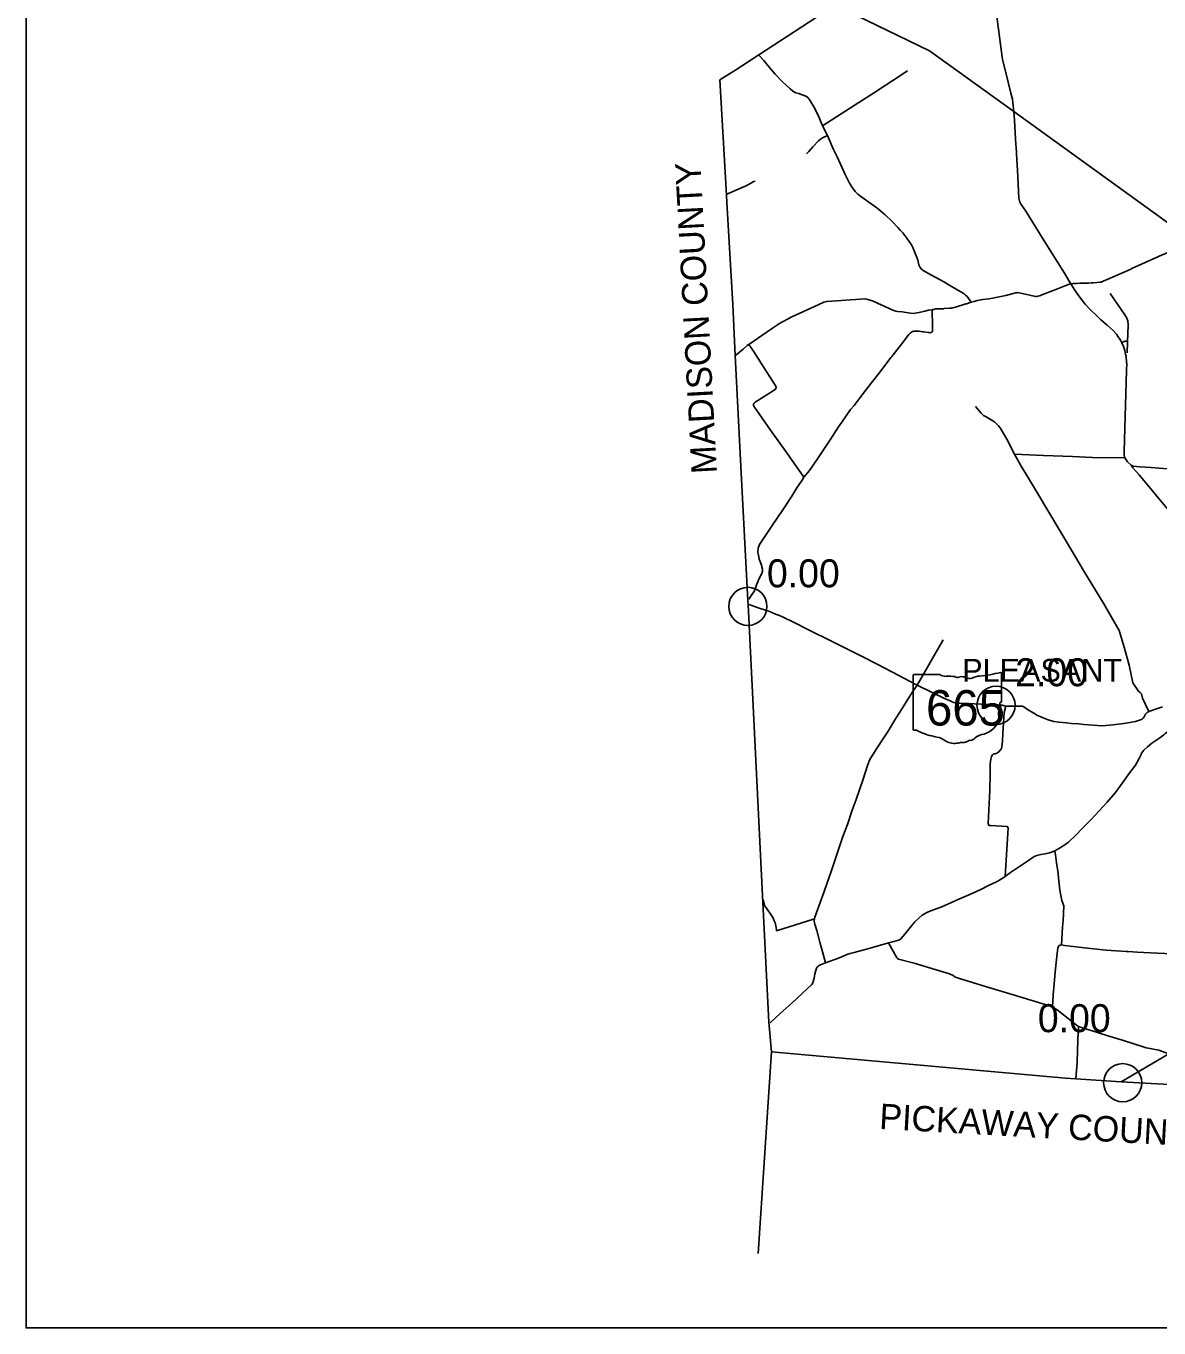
# Model space of a CAD drawing. Extents: x 1729596 to 1934326, y 644115 to 911751.
# Drawn here: x 1730291 to 1774831, y 650175 to 701344 of the extents above; entities that cross this region are included whole.
import ezdxf

# ---------------------------------------------------------------- set-up
doc = ezdxf.new("R2010")
doc.units = 0
for name, color, linetype in [('Default', 7, 'Continuous'), ('GM_X_Adjacent_County', 7, 'Continuous'), ('GM_X_Adjacent_County_Text', 7, 'Continuous'), ('GM_X_County', 7, 'Continuous'), ('GM_X_County_Road', 7, 'Continuous'), ('GM_X_Interstate_Route', 7, 'Continuous'), ('GM_X_State_Route', 7, 'Continuous'), ('GM_X_State_Shield', 7, 'Continuous'), ('GM_X_Township', 7, 'Continuous'), ('GM_X_Township_Road', 7, 'Continuous'), ('GM_X_Township_Text', 7, 'Continuous'), ('SC_Scratch1', 7, 'Continuous')]:
    doc.layers.add(name, color=color, linetype=linetype)

msp = doc.modelspace()

# ---------------------------------------------------------------- linework, layer by layer
at = {"layer": 'Default'}
for centre in [(1758669, 678534), (1758669, 678534), (1768427, 674646), (1773406, 659814), (1773406, 659814)]:
    msp.add_circle(centre, 750, dxfattribs=at)
at = {"layer": 'GM_X_Adjacent_County'}
msp.add_line((1759596, 661027), (1759070, 653104), dxfattribs=at)
at = {"layer": 'GM_X_County'}
msp.add_lwpolyline([(1779741, 659492), (1773339, 659850), (1771560, 659962), (1771157, 659994), (1759596, 661027), (1759497, 662188), (1759258, 666902), (1758681, 678614), (1758672, 678766), (1758400, 683790), (1758170, 688397), (1758072, 690399), (1757841, 694414), (1757825, 694698), (1757564, 699226), (1758151, 699596), (1759102, 700215), (1763614, 703154)], dxfattribs=at)
at = {"layer": 'GM_X_County_Road'}
for points in [[(1769211, 696603), (1769207, 696674), (1769146, 697650), (1769123, 697982), (1769092, 698322), (1769069, 698471), (1769011, 698712), (1768797, 699571), (1768694, 699972), (1768678, 700045), (1768665, 700116), (1768455, 701718), (1768288, 702977), (1767960, 705470), (1767928, 705663), (1767674, 707564), (1767277, 710453)], [(1759118, 700191), (1759294, 699984), (1759452, 699796), (1759742, 699454), (1760015, 699169), (1760338, 698875), (1760441, 698789), (1760561, 698723), (1760671, 698692), (1760765, 698659), (1760887, 698616), (1760969, 698580), (1761030, 698531), (1761109, 698430), (1761262, 698171), (1761420, 697873), (1761607, 697416), (1761797, 697046), (1762028, 696515), (1762193, 696174), (1762475, 695535), (1762665, 695168), (1762782, 694986), (1762885, 694840), (1762994, 694731), (1763149, 694620), (1763429, 694425), (1763735, 694193), (1764069, 693928), (1764328, 693677), (1764559, 693424), (1764661, 693319), (1764764, 693212), (1764913, 693007), (1765013, 692877), (1765097, 692743), (1765154, 692635), (1765262, 692379), (1765327, 692222), (1765370, 692084), (1765397, 691958), (1765440, 691859), (1765493, 691792), (1765563, 691736), (1765886, 691553), (1766395, 691275)], [(1771341, 691254), (1771115, 691633), (1770257, 693004), (1769593, 694062), (1769390, 694366), (1769356, 694426), (1769342, 694480), (1769332, 694523), (1769326, 694581), (1769266, 695683), (1769242, 696082), (1769211, 696603)], [(1774706, 692237), (1774843, 692298), (1775060, 692395), (1775439, 692564), (1775649, 692658), (1776021, 692821), (1776156, 692877), (1776219, 692908), (1776251, 692927)], [(1773694, 691781), (1773797, 691827), (1774289, 692049), (1774690, 692229), (1774706, 692237)], [(1768358, 690662), (1768483, 690686), (1768811, 690760), (1769103, 690838), (1769190, 690858), (1769240, 690864), (1769283, 690866), (1769921, 690727), (1769986, 690717), (1770030, 690718), (1770075, 690722), (1770123, 690737), (1770169, 690754), (1770226, 690777), (1770706, 690962), (1771174, 691144), (1771272, 691184), (1771368, 691209), (1771448, 691220), (1771547, 691228), (1771615, 691230), (1771714, 691235), (1772065, 691244), (1772161, 691249), (1772240, 691256), (1772393, 691269), (1772527, 691282), (1772563, 691289), (1772598, 691297), (1772640, 691312), (1772799, 691382), (1773694, 691781)], [(1766395, 691275), (1766548, 691191), (1766861, 691006), (1767113, 690862), (1767182, 690812), (1767229, 690772), (1767288, 690708), (1767355, 690619), (1767442, 690488)], [(1773556, 687811), (1773557, 687833), (1773562, 688067), (1773561, 688136), (1773540, 688359), (1773520, 688449), (1773486, 688588), (1773435, 688744), (1773371, 688887), (1773328, 688967), (1773293, 689031), (1773233, 689129), (1773156, 689234), (1773037, 689374), (1772791, 689590), (1772546, 689792), (1772359, 689981), (1772141, 690185), (1771936, 690415), (1771790, 690595), (1771640, 690799), (1771526, 690968), (1771368, 691209), (1771341, 691254)], [(1758190, 688407), (1758479, 688638), (1758648, 688783), (1758710, 688829), (1759599, 689437), (1759837, 689604), (1759887, 689640), (1760396, 689910), (1761431, 690392), (1761660, 690495), (1761773, 690522), (1763081, 690607), (1763271, 690616), (1763329, 690612), (1763472, 690575), (1763593, 690533), (1764374, 690183), (1764486, 690140), (1764554, 690126), (1764734, 690110), (1765064, 690056), (1765178, 690052), (1765245, 690059), (1765402, 690091), (1765631, 690139), (1765775, 690171), (1765914, 690192)], [(1766706, 690265), (1766732, 690270), (1766792, 690286), (1767243, 690423), (1767267, 690431)], [(1767267, 690431), (1767442, 690488), (1767569, 690522), (1767682, 690553), (1767828, 690587), (1767909, 690597), (1768158, 690628), (1768301, 690652), (1768358, 690662)], [(1765534, 689330), (1765581, 689323), (1765761, 689299), (1765801, 689293), (1765840, 689290), (1765871, 689293), (1765901, 689306), (1765915, 689322), (1765925, 689339), (1765928, 689362), (1765932, 689383), (1765933, 689417), (1765927, 689661), (1765922, 689841), (1765921, 689916), (1765919, 690042), (1765914, 690192)], [(1765914, 690192), (1765943, 690200), (1765975, 690208), (1766049, 690224), (1766117, 690233), (1766195, 690236), (1766368, 690236), (1766389, 690238)], [(1766389, 690238), (1766611, 690250), (1766671, 690257), (1766706, 690265)], [(1764315, 688347), (1764323, 688357), (1764668, 688790), (1765000, 689215), (1765046, 689269), (1765084, 689300), (1765107, 689315), (1765145, 689334), (1765168, 689343)], [(1765168, 689343), (1765174, 689345), (1765212, 689353), (1765234, 689357), (1765251, 689358), (1765270, 689358), (1765298, 689358), (1765328, 689356), (1765402, 689347), (1765534, 689330)], [(1759077, 680590), (1759061, 680668), (1759078, 680818), (1759131, 680968), (1759287, 681203), (1759631, 681711), (1760047, 682335), (1760404, 682872), (1760596, 683193), (1760806, 683496), (1760873, 683608), (1761094, 683872), (1761429, 684371), (1761902, 685082), (1762236, 685589), (1762361, 685777), (1762710, 686270), (1762844, 686434), (1763167, 686851), (1763522, 687306), (1763867, 687757), (1764291, 688315), (1764315, 688347)], [(1773735, 684084), (1773599, 684221), (1773485, 684370), (1773460, 684482), (1773459, 684627), (1773556, 687811)], [(1773735, 684084), (1773770, 684068), (1773823, 684048), (1774075, 684022), (1774528, 683999), (1776435, 683842), (1776845, 683820), (1777912, 683762), (1778599, 683726), (1779300, 683688), (1780237, 683632), (1781070, 683572), (1781206, 683562), (1782831, 683463), (1783987, 683396)], [(1778904, 678047), (1778314, 678671), (1777693, 679394), (1777072, 680120), (1776484, 680798), (1776345, 680960), (1775913, 681464), (1774048, 683702), (1773810, 683978), (1773735, 684084)], [(1759063, 679504), (1759105, 679598), (1759208, 679807), (1759243, 679915), (1759244, 680001), (1759197, 680198), (1759119, 680391), (1759084, 680555), (1759077, 680590)], [(1758707, 678813), (1758861, 679055), (1758919, 679123), (1758993, 679335), (1759023, 679416), (1759045, 679464), (1759063, 679504)], [(1761718, 664522), (1761629, 664869), (1761494, 665341), (1761375, 665791), (1761303, 666042), (1761289, 666098), (1761282, 666179), (1761289, 666249), (1761307, 666319), (1761667, 667325), (1761951, 668157), (1762115, 668630), (1762282, 669135), (1762409, 669489), (1762581, 669962), (1762769, 670526), (1762924, 670951), (1763200, 671744), (1763378, 672275), (1763468, 672511), (1763705, 672898), (1764033, 673400), (1764187, 673633), (1764477, 674115), (1764641, 674378), (1764908, 674799), (1765145, 675172), (1765320, 675443)], [(1774127, 672717), (1774135, 672735), (1774225, 672873), (1774380, 673020), (1774555, 673162), (1774867, 673370), (1775024, 673487), (1775070, 673535), (1775162, 673604)], [(1764301, 665332), (1764301, 665332), (1764605, 665414), (1764637, 665432), (1764681, 665467), (1764841, 665654), (1765105, 665985), (1765231, 666134), (1765390, 666285), (1765525, 666400), (1765726, 666517), (1765965, 666611), (1766290, 666724), (1766553, 666846), (1766958, 667023), (1767424, 667224), (1767830, 667409), (1768105, 667551), (1768475, 667728), (1768710, 667866), (1768782, 667924), (1768990, 668078), (1769267, 668258), (1769708, 668551), (1769929, 668698), (1769969, 668723), (1770035, 668747), (1770182, 668782), (1770362, 668814), (1770522, 668849), (1770641, 668890), (1770737, 668933), (1770926, 669032), (1771171, 669190), (1771276, 669273), (1771560, 669549), (1771828, 669820), (1772171, 670165), (1772801, 670835), (1773122, 671225), (1773401, 671599), (1773692, 672000), (1773906, 672294), (1774048, 672554), (1774113, 672689), (1774127, 672717)], [(1759547, 662165), (1759958, 662552), (1760412, 662957), (1761016, 663510), (1761167, 663661), (1761210, 663716), (1761240, 663796), (1761273, 663926), (1761307, 664090), (1761374, 664310), (1761405, 664366), (1761441, 664402), (1761529, 664445), (1761718, 664522), (1762230, 664712), (1762605, 664861), (1762694, 664895), (1762844, 664931), (1763478, 665102), (1764200, 665305), (1764301, 665332)], [(1764200, 665305), (1764508, 664749), (1764532, 664717), (1764549, 664699), (1764595, 664670), (1765211, 664507), (1766199, 664214), (1766592, 664095), (1766738, 664031), (1766806, 663977), (1766832, 663961), (1767023, 663901), (1768012, 663600), (1769058, 663279), (1770224, 662926), (1770486, 662848), (1770574, 662819), (1770642, 662787), (1770716, 662746), (1770829, 662675), (1771082, 662480), (1771512, 662142), (1771595, 662069), (1771631, 662047), (1771673, 662023), (1771823, 661973), (1772416, 661788), (1772823, 661656), (1773396, 661485), (1774251, 661212), (1774330, 661187)], [(1774330, 661187), (1774345, 661182), (1774826, 661093), (1775224, 660950), (1775426, 660892), (1775570, 660850)]]:
    msp.add_lwpolyline(points, dxfattribs=at)
at = {"layer": 'GM_X_Interstate_Route'}
msp.add_lwpolyline([(1773339, 659850), (1775224, 660950)], dxfattribs=at)
at = {"layer": 'GM_X_State_Route'}
for points in [[(1758718, 678605), (1758924, 678536), (1759155, 678456), (1759328, 678400), (1759455, 678358), (1759590, 678309), (1759762, 678235), (1759915, 678170), (1760033, 678118), (1760182, 678048), (1760356, 677962), (1761185, 677549), (1761857, 677219), (1762607, 676839), (1763166, 676560), (1763750, 676259), (1764361, 675943), (1765045, 675589), (1765320, 675443), (1766432, 674900), (1766528, 674860), (1766624, 674819), (1766707, 674783), (1766766, 674760), (1766836, 674741), (1766930, 674733), (1767316, 674714), (1767839, 674697), (1768338, 674685), (1768516, 674670), (1768673, 674646), (1768805, 674613), (1768981, 674615), (1769337, 674616), (1769425, 674616), (1769459, 674611), (1769494, 674600), (1769524, 674583), (1769666, 674488), (1769814, 674389), (1769977, 674293), (1770036, 674265)], [(1771677, 673914), (1771877, 673898), (1772593, 673840), (1773013, 673876), (1773444, 673930), (1773760, 673979), (1773909, 674015), (1774111, 674070), (1774175, 674101), (1774214, 674140), (1774245, 674198), (1774272, 674244), (1774303, 674298), (1774331, 674330), (1774372, 674364), (1774429, 674407), (1774779, 674519), (1774965, 674582)], [(1770036, 674265), (1770273, 674153), (1770470, 674076), (1770695, 674012), (1770898, 673985), (1771197, 673953), (1771395, 673937), (1771677, 673914)]]:
    msp.add_lwpolyline(points, dxfattribs=at)
at = {"layer": 'GM_X_State_Shield'}
for p, q in [((1765162, 675817), (1765162, 673703)), ((1766216, 675853), (1765196, 675853)), ((1768642, 674800), (1768642, 675905)), ((1768642, 674800), (1768642, 674800))]:
    msp.add_line(p, q, dxfattribs=at)
for centre, major_axis, start_param, end_param in [((1765202, 675821), (40.3, 0), 1.712693, 3.28349), ((1766458, 676098), (391, 0), 4.042523, 4.731795), ((1766588, 674667), (1404, 0), 1.404758, 1.657858), ((1766907, 675832), (113, 0), 3.836095, 5.185415), ((1767072, 675588), (235, 0), 0.950623, 2.079405), ((1767375, 675923), (282, 0), 4.081561, 5.145723), ((1767873, 675208), (743, 0), 1.699011, 2.107814), ((1767403, 678734), (3691, 0), 4.814394, 5.042369), ((1768604, 675910), (38.7, 0), 6.141152, 7.989035), ((1768781, 674337), (262, 0), 2.387724, 3.262537), ((1768633, 674719), (60, 0), 1.883978, 3.671073), ((1768252, 674579), (360, 0), 5.934695, 6.695948), ((1768601, 674796), (41.5, 0), 5.05454, 6.418171), ((1767609, 674197), (923, 0), 5.101752, 6.440018), ((1765202, 673699), (40.7, 0), 3.00124, 4.508301), ((1765208, 673915), (310, 0), 4.665946, 4.897461), ((1765272, 673581), (112, 0), 0.519207, 1.627899), ((1766685, 675480), (2665, 0), 4.195997, 4.488961), ((1765890, 672754), (834, 0), 0.823519, 1.323587), ((1767999, 673110), (506, 0), 1.647645, 2.488434), ((1766792, 673571), (529, 0), 4.026481, 4.996735), ((1767098, 672840), (435, 0), 1.495662, 1.94098), ((1767137, 673413), (282, 0), 4.691044, 5.507374), ((1767392, 673208), (79.4, 0), 1.147584, 2.315152), ((1767358, 673499), (298, 0), 4.937069, 5.64225)]:
    msp.add_ellipse(centre, major_axis=major_axis, ratio=0.8, start_param=start_param, end_param=end_param, dxfattribs=at)
at = {"layer": 'GM_X_Township'}
msp.add_lwpolyline([(1794587, 689062), (1792546, 689167), (1791461, 689213), (1784810, 689542), (1784632, 689548), (1783167, 689596), (1782688, 689618), (1780628, 689706), (1776861, 692396), (1776156, 692877), (1775926, 693071), (1769123, 697982), (1765814, 700371), (1762103, 702170)], dxfattribs=at)
at = {"layer": 'GM_X_Township_Road'}
for points in [[(1764374, 699207), (1764942, 699581)], [(1763805, 698834), (1764369, 699204), (1764374, 699207)], [(1761607, 697416), (1762893, 698246), (1763796, 698828), (1763805, 698834)], [(1760978, 696327), (1761064, 696416), (1761226, 696601), (1761447, 696837), (1761519, 696901), (1761600, 696946), (1761797, 697046)], [(1757848, 694731), (1758534, 695036), (1758575, 695056)], [(1758575, 695056), (1758693, 695112), (1758910, 695231), (1758955, 695252)], [(1773576, 688500), (1773591, 688930), (1773616, 689588), (1773609, 689759), (1773571, 689859), (1773483, 689996), (1772919, 690827)], [(1760873, 683608), (1760748, 683778), (1760228, 684530), (1759563, 685466), (1758910, 686401), (1758892, 686435), (1758888, 686477), (1758903, 686509), (1758959, 686555), (1759709, 687030), (1759753, 687066), (1759775, 687106), (1759784, 687140), (1759768, 687184), (1759419, 687739), (1758893, 688570), (1758710, 688829)], [(1773371, 688887), (1773405, 688925), (1773427, 688934), (1773450, 688944), (1773471, 688951), (1773505, 688954), (1773530, 688953), (1773565, 688946), (1773591, 688930)], [(1769171, 684488), (1769155, 684519), (1768844, 685102), (1768584, 685546), (1768524, 685625), (1768359, 685784), (1768174, 685907), (1768040, 685982), (1767938, 686041), (1767845, 686127), (1767612, 686391)], [(1769155, 684519), (1770290, 684471), (1771437, 684422), (1772218, 684388), (1773485, 684370)], [(1774429, 674407), (1774188, 674926), (1774139, 675101), (1774091, 675155), (1774025, 675200), (1773798, 675535), (1773663, 676229), (1773462, 676936), (1773264, 677586), (1772665, 678633), (1771860, 679950), (1771386, 680739), (1770061, 682979), (1769620, 683702), (1769410, 684045), (1769171, 684488)], [(1765320, 675443), (1766343, 677226)], [(1768782, 667924), (1768885, 669618), (1768902, 669820), (1768894, 669852), (1768879, 669876), (1768851, 669884), (1768219, 669922), (1768169, 669926), (1768139, 669936), (1768127, 669957), (1768117, 669999), (1768155, 670792), (1768179, 671312), (1768197, 671923), (1768200, 672352), (1768222, 672528), (1768242, 672630), (1768285, 672702), (1768327, 672737), (1768389, 672737), (1768461, 672760), (1768520, 672800), (1768603, 672892), (1768639, 672943), (1768659, 673013), (1768677, 673235), (1768691, 673554), (1768716, 673942), (1768745, 674359), (1768805, 674613)], [(1770996, 665230), (1771039, 665921), (1771065, 666186), (1771077, 666462), (1771093, 666764), (1771068, 666837), (1771009, 666979), (1770968, 667178), (1770940, 667377), (1770901, 667750), (1770849, 668125), (1770808, 668454), (1770760, 668767), (1770737, 668933)], [(1759265, 667013), (1759325, 666804), (1759328, 666798)], [(1759328, 666798), (1759369, 666719), (1759372, 666715), (1759626, 666342), (1759664, 666282), (1759709, 666178)], [(1759709, 666178), (1759734, 666118), (1759737, 666113), (1759777, 665920), (1759792, 665810), (1759798, 665786), (1760083, 665878), (1760753, 666081), (1761289, 666249)], [(1770642, 662787), (1770675, 663273), (1770765, 664287), (1770830, 664907), (1770857, 665105), (1770884, 665169), (1770914, 665205), (1770952, 665225), (1770996, 665230), (1771116, 665211), (1772026, 665102), (1772750, 665027), (1773538, 664969), (1773618, 664968), (1773976, 664951), (1774772, 664906), (1775927, 664855)], [(1771560, 659962), (1771611, 660607), (1771641, 661518), (1771673, 662023)]]:
    msp.add_lwpolyline(points, dxfattribs=at)
at = {"layer": 'SC_Scratch1'}
msp.add_lwpolyline([(1730291, 784675), (1926541, 784675), (1926541, 650175), (1730291, 650175)], close=True, dxfattribs=at)

# ---------------------------------------------------------------- texts
at = {"layer": 'Default'}
for s, p in [('0.00', (1759419, 679284)), ('2.00', (1769177, 675396)), ('0.00', (1770070, 661800))]:
    msp.add_text(s, height=1100, dxfattribs=at).set_placement(p)
at = {"layer": 'GM_X_Adjacent_County_Text'}
for s, rotation, p in [('MADISON COUNTY', 93.0522, (1757457, 683771)), ('PICKAWAY COUNTY', 356.8216, (1763818, 657997))]:
    msp.add_text(s, height=1000, rotation=rotation, dxfattribs=at).set_placement(p)
at = {"layer": 'GM_X_State_Shield'}
msp.add_text('665', height=1392.2, dxfattribs=at).set_placement((1765672, 673852))
at = {"layer": 'GM_X_Township_Text'}
msp.add_text('PLEASANT', height=900, rotation=0, dxfattribs=at).set_placement((1767095, 675573))

doc.saveas('drawing.dxf')
